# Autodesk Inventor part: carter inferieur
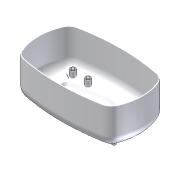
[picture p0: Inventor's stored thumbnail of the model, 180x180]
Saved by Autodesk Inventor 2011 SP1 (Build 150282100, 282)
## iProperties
Created: 2010-12
Part Number: carter inferieur
Document SubType Name: Modeling
Designer: eric
Density: 1 g/cm^3
Author: eric
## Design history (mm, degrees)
feature "Base1"
node "Solide1"
node "Corps solides"
node "Corps surfaciques"
